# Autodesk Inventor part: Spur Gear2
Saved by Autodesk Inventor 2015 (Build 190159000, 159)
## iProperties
Created: 2014-08
Part Number: Spur Gear2
Material: Steel
Document SubType Name: Modeling
Designer: User
Categories: <?xml version="1.0" encoding="UTF-16"?> <MemberInstance><Categories><FamilyTemplate><FamilyTemplateParameter ValueType="xs:double" Id="1" ObjectReferenceKey="da
Density: 1 g/cm^3
Appearance: Steel
CustomPartVersion: 1
Author: User
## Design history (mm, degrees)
sketch "Sketch1"
  geometry: C1 r 20.068 at (0, 0)
  constraints: 1 centre point
  dimensions: "d0" = 40.13641 diameter of C1 (= 1.1 x da_df)
extrude "Extrusion1" new body sketch "Sketch1" distance "d1" = 4 (= da_b); taper "d2" = 0 deg
workplane "Work Plane2"
sketch "Sketch2"
  geometry: C1 r 20.068 at (0, 0) reference; C2 r 17.25 at (0, 0)
  constraints: 1 centre point, 1 coincident
  dimensions: "d3" = 34.5 diameter of C2 (= da_dw)
feature "Pitch Diameter" sketch "Sketch2" dims "d4" = 10, "d5" = 0
workplane "Work Plane8"
workplane "Work Plane9"
feature "Spur Gear" dims "da_b" = 4, "da_d" = 34.46275, "da_z" = 330, "da_aw" = 11.5, "da_da" = 33.32412, "da_df" = 36.48764, "da_dw" = 34.5, "da_z2" = 110, "da_beta" = 40 deg, "da_lefttooth" = 0, "da_righttooth" = 10, "da_straighttooth" = 0
body "Solid1"
body "Srf1"
other parameters: "d16" = 11.5 (= da_aw), "d17" = 0, "d34" = 0.952 (computed from da_z), "d39" = 0, "d45" = 0, "d47" = 11.5 (= da_aw), "d50" = 0, "d51" = 0, "d52" = 11.5 (= da_aw)
